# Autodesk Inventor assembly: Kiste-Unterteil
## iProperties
Manager: Dr.-Ing. Roland Schröder
Company: www.Das-Entwicklungsbuero.de
Created: 2006-09
Part Number: Kiste-Unterteil
Project: 12107
Document SubType Name: Assembly
Designer: rsc
Engineer: Dr.-Ing. Roland Schröder
Oberflächen: Ra 3,2
Toleranzen: ISO 2768 - m
a: 17.000 oE
b: 10.000 mm
d: 34.000 mm
Author: rsc
